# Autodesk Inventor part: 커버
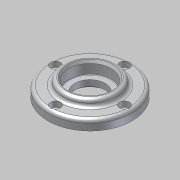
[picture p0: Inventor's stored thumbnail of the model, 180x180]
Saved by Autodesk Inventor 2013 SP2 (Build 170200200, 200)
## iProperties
Created: 2014-03
Part Number: 커버
Document SubType Name: Modeling
Designer: SeoGD™[esajin.kr]
Density: 1 g/cm^3
Material: 일반
Author: SeoGD™[esajin.kr]
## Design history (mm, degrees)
sketch "스케치1"
  geometry: C1 r 25 at (0, 0) reference; C2 r 16 at (0, 0) reference; 1 further point
  node "참조1"
  node "참조2"
extrude "돌출1" new body sketch "스케치1" distance "d0" = 6; taper "d1" = 0 deg
extrude "돌출2" join sketch "스케치1" distance "d2" = 3; taper "d3" = 0 deg
sketch "스케치2"
  geometry: C1 r 1.23 at (0, 20.5) reference; 1 further point
hole "구멍1" sketch "스케치2" at (0, 20.5) diameter "d4" = 3.4; stored, may be unused: countersink angle "d8" = 90 deg, drill point angle "d10" = 118 deg; dims "d5" = 6, "d6" = 6, "d7" = 3.3, "d9" = 8
sketch "스케치3"
  geometry: C1 r 16 at (0, 0); 1 further point
  constraints: 1 centre point, 1 coincident
  dimensions: "d11" = 32 diameter of C1
extrude "돌출3" join sketch "스케치3" distance "d12" = 4; taper "d13" = 0 deg
fillet "모깎기1" dims "d14" = 2
hole "구멍2" diameter "d17" = 18; stored, may be unused: countersink angle "d21" = 90 deg, drill point angle "d23" = 118 deg; dims "d15" = 10, "d16" = 10, "d18" = 6, "d19" = 25, "d20" = 7.5, "d22" = 8
chamfer "모따기1" distance "d30" = 1.6; stored, may be unused: second distance "d31" = 2, angle "d32" = 30 deg
fillet "모깎기2" dims "d33" = 0.3
sketch "스케치4"
  geometry: C1 r 16 at (0, 0) reference; C2 r 11.5 at (0, 0); 1 further point
  constraints: 1 centre point, 1 coincident
  dimensions: "d34" = 23 diameter of C2
extrude "돌출4" cut sketch "스케치4" distance "d35" = 2; taper "d36" = 0 deg
fillet "모깎기3" dims "d37" = 3
chamfer "모따기2" distance "d38" = 0.5; stored, may be unused: second distance "d39" = 2, angle "d40" = 45 deg
node "솔리드1"
pattern_circular "원형 패턴2" dims angle "d28" = 360 deg
node "참조3"
